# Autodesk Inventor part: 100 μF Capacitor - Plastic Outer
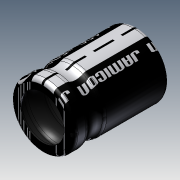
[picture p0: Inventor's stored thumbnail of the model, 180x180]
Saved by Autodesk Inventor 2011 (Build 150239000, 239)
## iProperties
Created: 2013-03
Part Number: 100 μF Capacitor - Plastic Outer
Material: ABS Plastic
Document SubType Name: Modeling
Designer: Lance
Mass: 0.069542 g
Surface Area: 6.63135 cm^2
Volume: 0.0656056 cm^3
Density: 1.06 g/cm^3
Author: Lance
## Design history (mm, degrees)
node "100 uF Capacitor - Shell Shape" dims "d0" = 10
sketch "Sketch1"
  geometry: C1 r 2.75 at (0, 0); 1 further point
  constraints: 1 centre point, 1 coincident
  dimensions: "d1" = 5.5 diameter of C1
extrude "Extrusion1" cut sketch "Sketch1" stored distance "d2" = 10; taper "d3" = 0 deg
workplane "Work Plane1"
workplane "Work Plane2"
sketch "Sketch3"
  geometry: L1 (-11.494, 5.196)-(11.494, 5.196); L2 (11.494, 5.196)-(11.494, -8.804); L3 (11.494, -8.804)-(-11.494, -8.804); L4 (-11.494, -8.804)-(-11.494, 5.196); 3 further points; 1 other entity
  constraints: 2 midpoint, 1 horizontal alignment, 1 vertical alignment, 2 other
  dimensions: "d22" = 14 distance between parallel lines of L3 L1
feature "Decal2" sketch "Sketch3"
sketch "Sketch2"
  geometry: L1 (-9.852, 4.196)-(9.852, 4.196); L2 (9.852, 4.196)-(9.852, -7.804); L3 (9.852, -7.804)-(-9.852, -7.804); L4 (-9.852, -7.804)-(-9.852, 4.196); 3 further points; 1 other entity
  constraints: 2 midpoint, 1 horizontal, 1 horizontal alignment, 1 vertical alignment, 2 other
  dimensions: "d20" = 12 distance between parallel lines of L3 L1
feature "Decal1" sketch "Sketch2"
feature "Solid1::100 μF Capacitor - Shell Shape.ipt" dims "d0" = 10
tag "TaggingFeature1"
node "Image1"
node "Image2"
body "Solid1"
